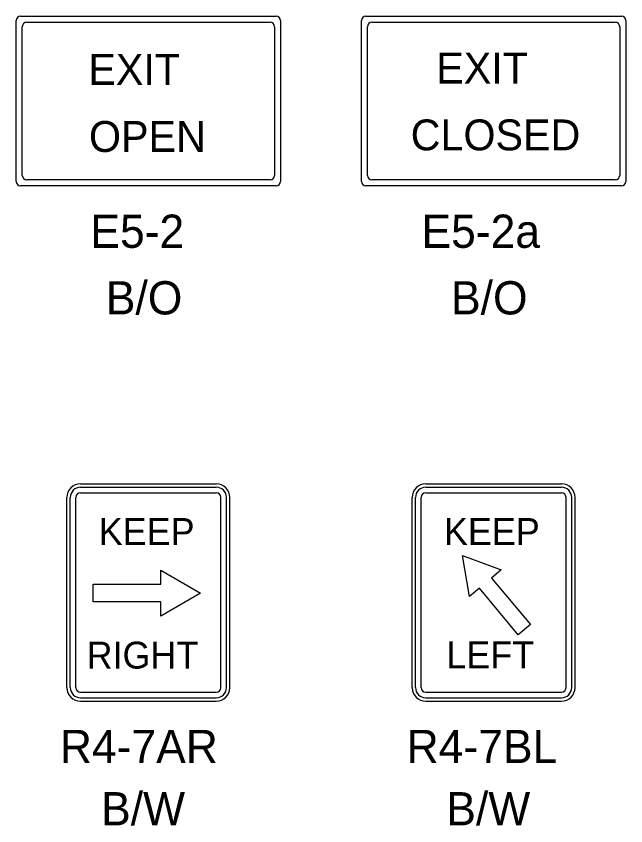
# Model space of a CAD drawing. Extents: x 10000 to 10794, y 10000 to 10499.
# Drawn here: x 10035.8 to 10100, y 10408.8 to 10494 of the extents above; entities that cross this region are included whole.
import ezdxf

# ---------------------------------------------------------------- set-up
doc = ezdxf.new("R2010")
doc.units = 0
for name, color, linetype in [('DSDate', 7, 'Continuous'), ('DSIndex', 7, 'Continuous'), ('DSText', 7, 'Continuous'), ('PlotBorder_dp', 7, 'Continuous')]:
    doc.layers.add(name, color=color, linetype=linetype)

msp = doc.modelspace()

# ---------------------------------------------------------------- linework, layer by layer
at = {"layer": 'DSDate'}
for p, q in [((10036.402, 10489.96), (10036.402, 10492.918)), ((10036.866, 10493.382), (10062.5, 10493.382)), ((10062.964, 10492.918), (10062.964, 10489.801)), ((10072.769, 10489.96), (10072.769, 10492.918)), ((10073.233, 10493.382), (10098.866, 10493.382)), ((10099.331, 10492.918), (10099.331, 10489.801)), ((10036.402, 10477.259), (10036.402, 10490.013)), ((10062.964, 10490.013), (10062.964, 10477.259)), ((10072.769, 10477.26), (10072.769, 10490.013)), ((10099.331, 10490.013), (10099.331, 10477.26)), ((10062.5, 10476.795), (10036.866, 10476.795)), ((10098.866, 10476.796), (10073.233, 10476.796))]:
    msp.add_line(p, q, dxfattribs=at)
for centre, start, end in [((10036.867, 10492.916), 90, 180), ((10062.5, 10492.916), 0, 90), ((10073.233, 10492.916), 90, 180), ((10098.866, 10492.916), 0, 90), ((10036.867, 10477.258), 180, 270), ((10062.5, 10477.258), 270, 0), ((10073.233, 10477.258), 180, 270), ((10098.866, 10477.258), 270, 0)]:
    msp.add_arc(centre, 0.464, start, end, dxfattribs=at)
at = {"layer": 'DSIndex'}
for p, q in [((10042.532, 10444.781), (10056.836, 10444.781)), ((10042.532, 10444.423), (10056.836, 10444.423)), ((10078.898, 10444.781), (10093.202, 10444.781)), ((10078.898, 10444.423), (10093.202, 10444.423)), ((10041.101, 10423.324), (10041.101, 10443.351)), ((10041.101, 10423.324), (10041.101, 10443.351)), ((10041.458, 10423.324), (10041.458, 10443.351)), ((10042.055, 10423.324), (10042.055, 10443.351)), ((10042.532, 10443.828), (10056.836, 10443.828)), ((10057.313, 10423.324), (10057.313, 10443.351)), ((10057.908, 10423.324), (10057.908, 10443.351)), ((10058.267, 10423.324), (10058.267, 10443.351)), ((10077.467, 10423.324), (10077.467, 10443.351)), ((10077.824, 10423.324), (10077.824, 10443.351)), ((10078.422, 10423.324), (10078.422, 10443.351)), ((10078.898, 10443.828), (10093.202, 10443.828)), ((10093.68, 10423.324), (10093.68, 10443.351)), ((10094.274, 10423.324), (10094.274, 10443.351)), ((10094.633, 10423.324), (10094.633, 10443.351)), ((10042.532, 10422.847), (10056.836, 10422.847)), ((10078.898, 10422.847), (10093.202, 10422.847)), ((10042.532, 10422.251), (10056.836, 10422.251)), ((10078.898, 10422.251), (10093.202, 10422.251)), ((10042.532, 10421.893), (10056.836, 10421.893)), ((10078.898, 10421.893), (10093.202, 10421.893))]:
    msp.add_line(p, q, dxfattribs=at)
for points in [[(10089.946, 10429.978), (10088.649, 10428.889), (10084.551, 10433.797), (10083.52, 10432.932), (10082.764, 10437.22), (10086.855, 10435.729), (10085.825, 10434.863)], [(10043.879, 10432.339), (10043.879, 10434.22), (10050.982, 10434.204), (10050.982, 10435.699), (10055.172, 10433.28), (10050.982, 10430.862), (10050.982, 10432.356)]]:
    msp.add_lwpolyline(points, close=True, dxfattribs=at)
for centre, radius, start, end in [((10042.53, 10443.351), 1.43, 90, 180), ((10042.53, 10443.351), 1.073, 90, 180), ((10056.835, 10443.351), 1.43, 0, 90), ((10056.835, 10443.351), 1.073, 0, 90), ((10078.896, 10443.351), 1.43, 90, 180), ((10078.896, 10443.351), 1.073, 90, 180), ((10093.201, 10443.351), 1.43, 0, 90), ((10093.201, 10443.351), 1.073, 0, 90), ((10042.53, 10443.351), 0.477, 90, 180), ((10056.835, 10443.351), 0.477, 0, 90), ((10078.896, 10443.351), 0.477, 90, 180), ((10093.201, 10443.351), 0.477, 0, 90), ((10042.53, 10423.324), 1.43, 180, 270), ((10042.53, 10423.324), 1.073, 180, 270), ((10042.53, 10423.324), 0.477, 180, 270), ((10056.835, 10423.324), 1.43, 270, 0), ((10056.835, 10423.324), 1.073, 270, 0), ((10056.835, 10423.324), 0.477, 270, 0), ((10078.896, 10423.324), 1.43, 180, 270), ((10078.896, 10423.324), 1.073, 180, 270), ((10078.896, 10423.324), 0.477, 180, 270), ((10093.201, 10423.324), 1.43, 270, 0), ((10093.201, 10423.324), 1.073, 270, 0), ((10093.201, 10423.324), 0.477, 270, 0)]:
    msp.add_arc(centre, radius, start, end, dxfattribs=at)
at = {"layer": 'DSText'}
for p, q in [((10035.756, 10489.925), (10035.756, 10493.558)), ((10036.22, 10494.022), (10063.146, 10494.022)), ((10063.611, 10493.558), (10063.611, 10489.889)), ((10072.122, 10489.925), (10072.122, 10493.558)), ((10072.586, 10494.023), (10099.513, 10494.023)), ((10099.977, 10493.558), (10099.977, 10489.89)), ((10035.756, 10476.612), (10035.756, 10490.013)), ((10063.611, 10490.013), (10063.611, 10476.612)), ((10072.122, 10476.613), (10072.122, 10490.013)), ((10099.977, 10490.013), (10099.977, 10476.613)), ((10063.146, 10476.148), (10036.22, 10476.148)), ((10099.513, 10476.149), (10072.586, 10476.149))]:
    msp.add_line(p, q, dxfattribs=at)
for centre, start, end in [((10036.22, 10493.557), 90, 180), ((10063.147, 10493.557), 0, 90), ((10072.586, 10493.557), 90, 180), ((10099.513, 10493.557), 0, 90), ((10036.22, 10476.612), 180, 270), ((10063.147, 10476.612), 270, 360), ((10072.586, 10476.612), 180, 270), ((10099.513, 10476.612), 270, 360)]:
    msp.add_arc(centre, 0.464, start, end, dxfattribs=at)

# ---------------------------------------------------------------- texts
at = {"layer": 'DSIndex'}
for s, height, p in [('KEEP', 2.8308, (10044.448, 10438.343)), ('KEEP', 2.8308, (10080.814, 10438.343)), ('RIGHT', 2.8308, (10043.173, 10425.329)), ('LEFT', 2.8308, (10081.069, 10425.369)), ('R4-7AR', 3.5, (10040.358, 10415.375)), ('R4-7BL', 3.5, (10076.89, 10415.375)), ('B/W', 3.5, (10044.702, 10408.821)), ('B/W', 3.5, (10081.068, 10408.821))]:
    msp.add_text(s, height=height, dxfattribs=at).set_placement(p)
at = {"layer": 'PlotBorder_dp'}
for s, height, p in [('EXIT', 3.2498, (10080.008, 10486.935)), ('EXIT', 3.2498, (10043.357, 10486.791)), ('OPEN', 3.2498, (10043.424, 10479.732)), ('CLOSED', 3.2498, (10077.316, 10479.899)), ('E5-2', 3.5, (10043.57, 10469.63)), ('E5-2a', 3.5, (10078.452, 10469.63)), ('B/O', 3.5, (10045.199, 10462.619)), ('B/O', 3.5, (10081.565, 10462.619))]:
    msp.add_text(s, height=height, dxfattribs=at).set_placement(p)

doc.saveas('drawing.dxf')
